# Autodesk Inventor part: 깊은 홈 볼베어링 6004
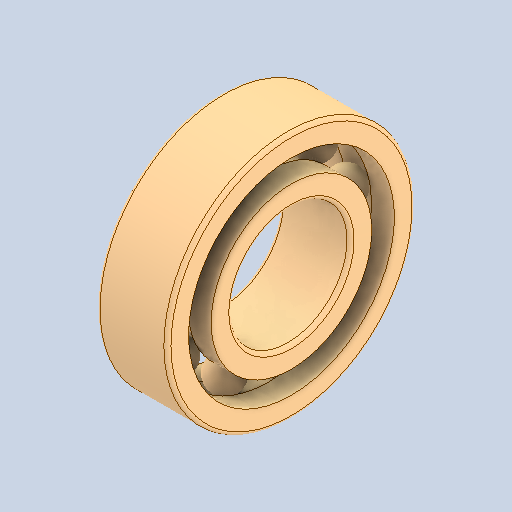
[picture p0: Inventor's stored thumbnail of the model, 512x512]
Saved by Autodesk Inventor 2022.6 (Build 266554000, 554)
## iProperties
Created: 2024-09
Part Number: 깊은 홈 볼베어링 6004
Material: 강철, 연강
Description: 깊은 그루브 볼 베어링
Document SubType Name: Modeling
Designer: Class 001
Density: 7.85 g/cm^3
Appearance: 기본값
Author: jhkim
Sending System: Autodesk Inventor 2025
Preprocessor: ST-DEVELOPER v20
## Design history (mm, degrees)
feature "Solid1"
feature "Solid1:1"
feature "Solid1:2"
feature "Solid1:3"
feature "Solid1:4"
feature "Solid1:5"
feature "Solid1:6"
feature "Solid1:7"
feature "Solid1:8"
feature "Solid1:9"
feature "Solid1:10"
node "솔리드1"
node "솔리드2"
node "솔리드3"
node "솔리드4"
node "솔리드5"
node "솔리드6"
node "솔리드7"
node "솔리드8"
node "솔리드9"
node "솔리드10"
node "솔리드11"
